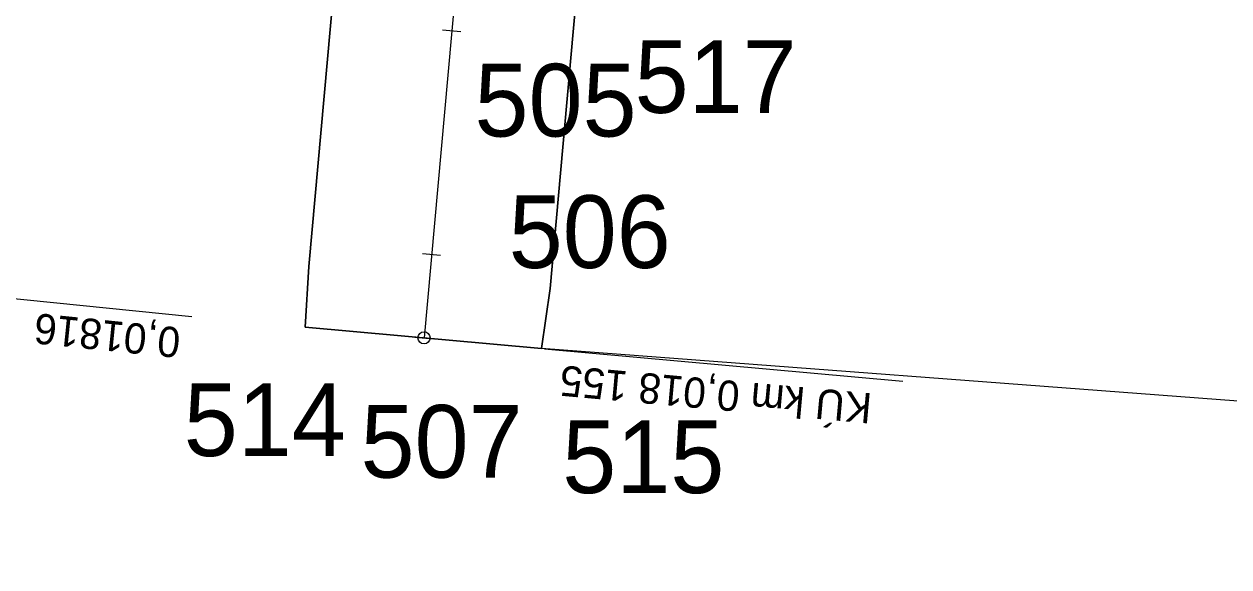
# Model space of a CAD drawing. Extents: x -747612 to -743169, y -1131726 to -1127091.
# Drawn here: x -747601.59 to -747581.69, y -1131718.63 to -1131709.67 of the extents above; entities that cross this region are included whole.
import ezdxf

# ---------------------------------------------------------------- set-up
doc = ezdxf.new("R2010")
doc.units = 0
for name, color, linetype in [('bublina_fialová_čára_tenká', 7, 'Continuous'), ('C3D_Trasa-Popisy trasy', 7, 'Continuous'), ('KOMUNIKACE_UPRAVA', 7, 'Continuous'), ('křížek', 7, 'Continuous'), ('OSA_KOMUNIKACE', 7, 'Continuous'), ('POP_OBLOUKY', 7, 'Continuous'), ('SKLONOVNIKY', 7, 'Continuous'), ('Vrstva 60', 7, 'Continuous')]:
    doc.layers.add(name, color=color, linetype=linetype)

# ---------------------------------------------------------------- blocks, each defined once
blk = doc.blocks.new('AeccTickCircle')
blk.add_circle((0, 0), 0.5)
blk = doc.blocks.new('POINT_DISPLAY')
blk.add_line((0, 0), (0, 0))

msp = doc.modelspace()

# ---------------------------------------------------------------- linework, layer by layer
at = {"layer": 'bublina_fialová_čára_tenká'}
msp.add_line((-747545.254, -1131718.632), (-747593.043, -1131715.025), dxfattribs=at)
at = {"layer": 'C3D_Trasa-Popisy trasy'}
for p, q in [((-747594.674, -1131709.764), (-747594.375, -1131709.791)), ((-747595.007, -1131713.457), (-747594.708, -1131713.484)), ((-747595.131, -1131714.837), (-747594.832, -1131714.864))]:
    msp.add_line(p, q, dxfattribs=at)
at = {"layer": 'KOMUNIKACE_UPRAVA'}
for points in [[(-747592.446, -1131708.996), (-747596.376, -1131708.045), (-747596.884, -1131713.675), (-747596.943, -1131714.673), (-747593.043, -1131715.025), (-747592.9, -1131714.034), (-747592.446, -1131708.996)], [(-747596.376, -1131708.045), (-747596.884, -1131713.675), (-747596.376, -1131708.045), (-747592.446, -1131708.996), (-747592.9, -1131714.034), (-747593.043, -1131715.025), (-747596.943, -1131714.673), (-747596.884, -1131713.675)]]:
    msp.add_lwpolyline(points, dxfattribs=at)
at = {"layer": 'OSA_KOMUNIKACE'}
msp.add_lwpolyline([(-747593.352, -1131696.768), (-747594.982, -1131714.85)], dxfattribs=at)
at = {"layer": 'POP_OBLOUKY'}
msp.add_line((-747592.99, -1131715.03), (-747587.076, -1131715.563), dxfattribs=at)
at = {"layer": 'SKLONOVNIKY'}
msp.add_line((-747598.817, -1131714.503), (-747602.797, -1131714.101), dxfattribs=at)
at = {"layer": 'Vrstva 60'}
for p, q in [((-747594.525, -1131709.778), (-747594.525, -1131709.778)), ((-747594.857, -1131713.471), (-747594.857, -1131713.471)), ((-747596.943, -1131714.673), (-747596.943, -1131714.673)), ((-747594.982, -1131714.85), (-747594.982, -1131714.85)), ((-747593.043, -1131715.025), (-747593.043, -1131715.025))]:
    msp.add_line(p, q, dxfattribs=at)

# ---------------------------------------------------------------- block references
at = {"layer": 'křížek', "xscale": 10, "yscale": 10, "rotation": 61.14491455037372}
for p in [(-747594.525, -1131709.778), (-747594.857, -1131713.471), (-747596.943, -1131714.673), (-747594.982, -1131714.85), (-747593.043, -1131715.025)]:
    msp.add_blockref('POINT_DISPLAY', p, dxfattribs=at)
at = {"layer": 'POP_OBLOUKY', "xscale": 0.19999999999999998, "yscale": 0.2, "rotation": -95.14959431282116}
msp.add_blockref('AeccTickCircle', (-747594.982, -1131714.85), dxfattribs=at)

# ---------------------------------------------------------------- texts
at = {"layer": 'POP_OBLOUKY'}
msp.add_text('KÚ km 0,018 155', height=0.5, rotation=174.8504, dxfattribs=at).set_placement((-747587.567, -1131715.769))
at = {"layer": 'SKLONOVNIKY'}
msp.add_text('0,01816', height=0.5, rotation=174.2192, dxfattribs=at).set_placement((-747598.987, -1131714.686))
at = {"layer": 'Vrstva 60'}
for s, p in [('517', (-747591.504, -1131711.136)), ('505', (-747594.148, -1131711.526)), ('506', (-747593.584, -1131713.697)), ('514', (-747598.95, -1131716.802)), ('507', (-747596.03, -1131717.159)), ('515', (-747592.699, -1131717.414))]:
    msp.add_text(s, height=1.2, dxfattribs=at).set_placement(p)

doc.saveas('drawing.dxf')
